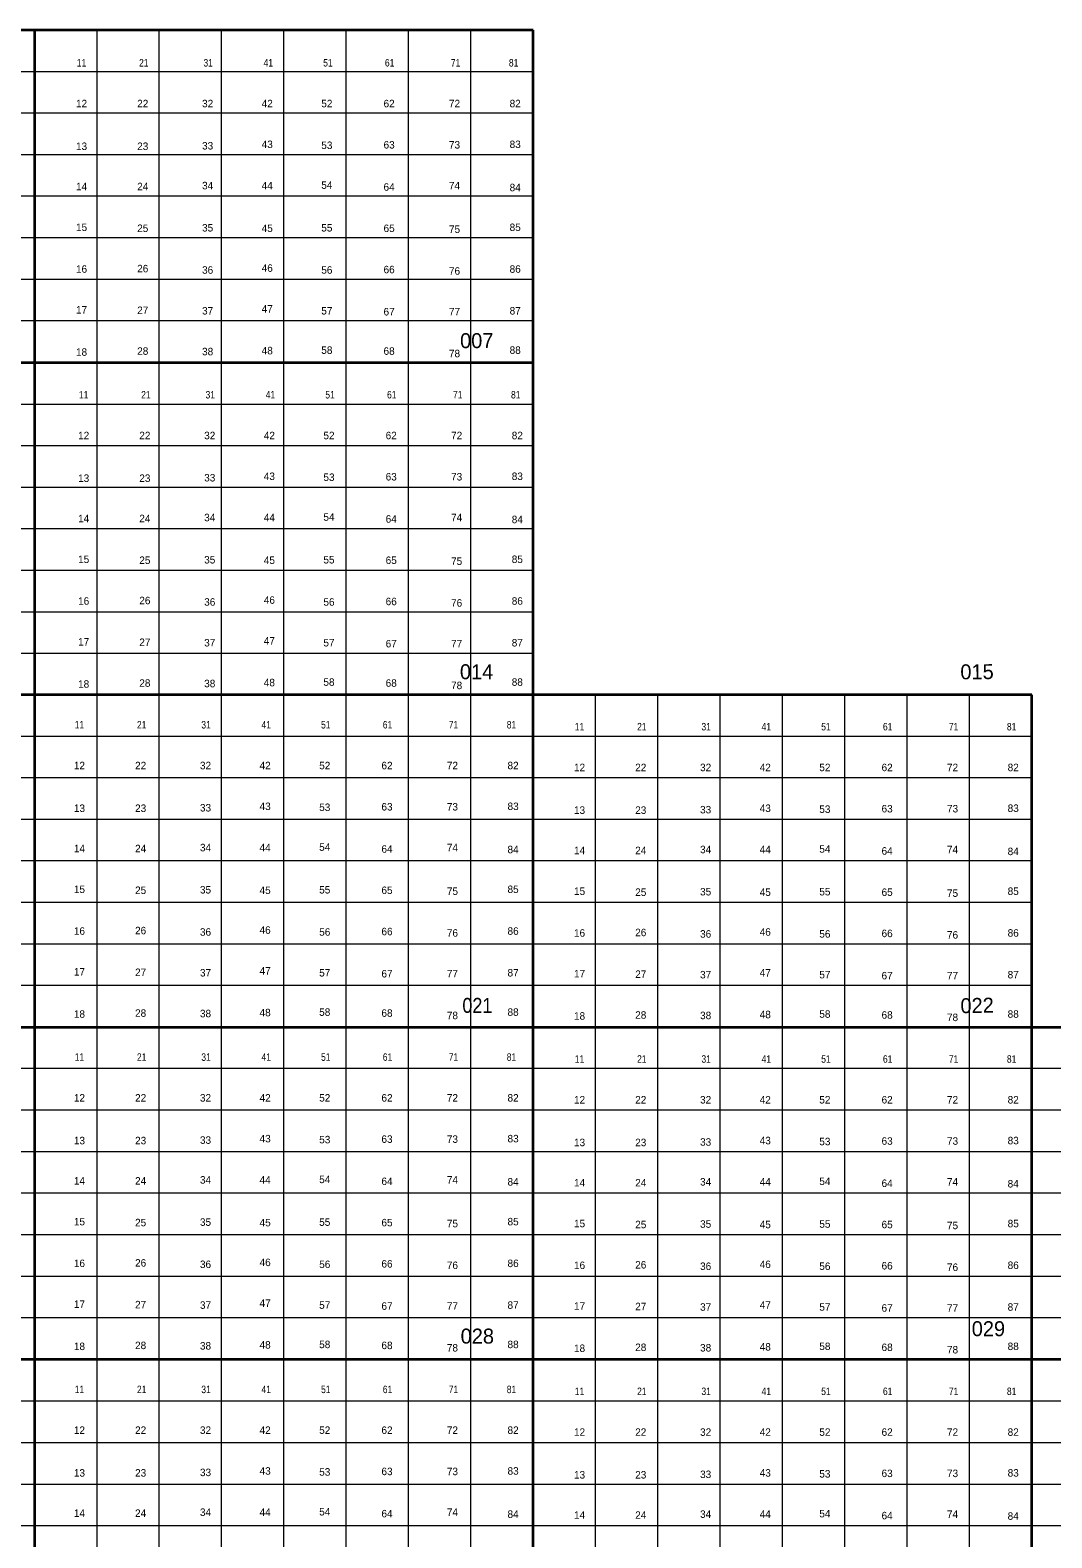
# Model space of a CAD drawing. Extents: x 639000 to 672000, y 222000 to 252000.
# Drawn here: x 653973 to 660121, y 242926 to 252000 of the extents above; entities that cross this region are included whole.
import ezdxf
from ezdxf.enums import TextEntityAlignment as Align

# ---------------------------------------------------------------- set-up
doc = ezdxf.new("R2010")
doc.units = 0
doc.header["$LTSCALE"] = 18
doc.layers.add('1', color=7, linetype='Continuous', lineweight=13)
doc.layers.add('2', color=7, linetype='Continuous')
doc.layers.add('29', color=7, linetype='Continuous')

msp = doc.modelspace()

# ---------------------------------------------------------------- linework, layer by layer
at = {"layer": '1', "lineweight": 35}
for p, q in [((657000, 252000), (648000, 252000)), ((654000, 222000), (654000, 252000)), ((657000, 222000), (657000, 252000)), ((645000, 250000), (657000, 250000)), ((660000, 248000), (639000, 248000)), ((660000, 222000), (660000, 248000)), ((639000, 246000), (663000, 246000)), ((666000, 244000), (639000, 244000))]:
    msp.add_line(p, q, dxfattribs=at)
at = {"layer": '1'}
for p, q in [((654375, 222000), (654375, 252000)), ((654750, 222000), (654750, 252000)), ((655125, 222000), (655125, 252000)), ((655500, 222000), (655500, 252000)), ((655875, 222000), (655875, 252000)), ((656250, 222000), (656250, 252000)), ((656625, 222000), (656625, 252000)), ((657000, 251750), (648000, 251750)), ((657000, 251500), (648000, 251500)), ((657000, 251250), (648000, 251250)), ((657000, 251000), (648000, 251000)), ((657000, 250750), (648000, 250750)), ((657000, 250500), (648000, 250500)), ((657000, 250250), (648000, 250250)), ((645000, 249750), (657000, 249750)), ((645000, 249500), (657000, 249500)), ((645000, 249250), (657000, 249250)), ((645000, 249000), (657000, 249000)), ((645000, 248750), (657000, 248750)), ((645000, 248500), (657000, 248500)), ((645000, 248250), (657000, 248250)), ((657375, 222000), (657375, 248000)), ((657750, 222000), (657750, 248000)), ((658125, 222000), (658125, 248000)), ((658500, 222000), (658500, 248000)), ((658875, 222000), (658875, 248000)), ((659250, 222000), (659250, 248000)), ((659625, 222000), (659625, 248000)), ((660000, 247750), (639000, 247750)), ((660000, 247500), (639000, 247500)), ((660000, 247250), (639000, 247250)), ((660000, 247000), (639000, 247000)), ((660000, 246750), (639000, 246750)), ((660000, 246500), (639000, 246500)), ((660000, 246250), (639000, 246250)), ((663000, 245750), (639000, 245750)), ((663000, 245500), (639000, 245500)), ((663000, 245250), (639000, 245250)), ((663000, 245000), (639000, 245000)), ((663000, 244750), (639000, 244750)), ((663000, 244500), (639000, 244500)), ((663000, 244250), (639000, 244250)), ((639000, 243750), (666000, 243750)), ((639000, 243500), (666000, 243500)), ((639000, 243250), (666000, 243250)), ((639000, 243000), (666000, 243000))]:
    msp.add_line(p, q, dxfattribs=at)

# ---------------------------------------------------------------- texts
at = {"layer": '2'}
for s, rotation, p in [('007', 0.15, (656660.31, 250086.42)), ('015', 0.43, (659670.93, 248093.82)), ('022', 1.29, (659672.21, 246085.5)), ('028', 359.94, (656663.46, 244095.54)), ('029', 359.94, (659739.05, 244140.04))]:
    msp.add_text(s, height=90, rotation=rotation, dxfattribs=at).set_placement(p, align=Align.CENTER)
msp.add_text('014', height=90, dxfattribs=at).set_placement((656659.17, 248093.9), align=Align.CENTER)
at = {"layer": '2', "width": 0.9}
msp.add_text('021', height=90, dxfattribs=at).set_placement((656663.84, 246085.74), align=Align.CENTER)
at = {"layer": '29', "width": 0.85}
for s, p in [('11', (654281.97, 251781.19)), ('21', (654656.57, 251781.19)), ('31', (655043.88, 251781.19)), ('41', (655405.78, 251781.19)), ('51', (655764.51, 251781.19)), ('61', (656135.94, 251781.19)), ('71', (656532.77, 251781.19)), ('81', (656881.97, 251781.19)), ('11', (654294.67, 249783.43)), ('21', (654669.27, 249783.43)), ('31', (655056.57, 249783.43)), ('41', (655418.48, 249783.43)), ('51', (655777.21, 249783.43)), ('61', (656148.64, 249783.43)), ('71', (656545.46, 249783.43)), ('81', (656894.67, 249783.43)), ('11', (654269.27, 247797.21)), ('21', (654643.88, 247797.21)), ('31', (655031.18, 247797.21)), ('41', (655393.08, 247797.21)), ('51', (655751.81, 247797.21)), ('61', (656123.24, 247797.21)), ('71', (656520.07, 247797.21)), ('81', (656869.28, 247797.21)), ('11', (657278.8, 247785.66)), ('21', (657653.4, 247785.66)), ('31', (658040.7, 247785.66)), ('41', (658402.61, 247785.66)), ('51', (658761.34, 247785.66)), ('61', (659132.77, 247785.66)), ('71', (659529.6, 247785.66)), ('81', (659878.8, 247785.66)), ('11', (654269.27, 245797.21)), ('21', (654643.88, 245797.21)), ('31', (655031.18, 245797.21)), ('41', (655393.08, 245797.21)), ('51', (655751.81, 245797.21)), ('61', (656123.24, 245797.21)), ('71', (656520.07, 245797.21)), ('81', (656869.28, 245797.21)), ('11', (657278.8, 245785.66)), ('21', (657653.4, 245785.66)), ('31', (658040.7, 245785.66)), ('41', (658402.61, 245785.66)), ('51', (658761.34, 245785.66)), ('61', (659132.77, 245785.66)), ('71', (659529.6, 245785.66)), ('81', (659878.8, 245785.66)), ('11', (654269.27, 243797.21)), ('21', (654643.88, 243797.21)), ('31', (655031.18, 243797.21)), ('41', (655393.08, 243797.21)), ('51', (655751.81, 243797.21)), ('61', (656123.24, 243797.21)), ('71', (656520.07, 243797.21)), ('81', (656869.28, 243797.21)), ('11', (657278.8, 243785.66)), ('21', (657653.4, 243785.66)), ('31', (658040.7, 243785.66)), ('41', (658402.61, 243785.66)), ('51', (658761.34, 243785.66)), ('61', (659132.77, 243785.66)), ('71', (659529.6, 243785.66)), ('81', (659878.8, 243785.66))]:
    msp.add_text(s, height=45, dxfattribs=at).set_placement(p, align=Align.CENTER)
at = {"layer": '29'}
for s, p in [('12', (654281.97, 251535.8)), ('22', (654650.22, 251535.8)), ('32', (655040.7, 251535.8)), ('42', (655399.43, 251535.8)), ('52', (655758.16, 251535.8)), ('62', (656132.76, 251535.8)), ('72', (656526.42, 251535.8)), ('82', (656891.5, 251535.8)), ('13', (654281.97, 251278.86)), ('23', (654650.22, 251278.86)), ('33', (655040.7, 251281.75)), ('43', (655399.43, 251290.41)), ('53', (655758.16, 251284.64)), ('63', (656132.77, 251287.53)), ('73', (656526.42, 251287.53)), ('83', (656891.5, 251290.41)), ('14', (654281.97, 251036.36)), ('24', (654650.22, 251036.36)), ('34', (655040.7, 251042.14)), ('44', (655399.43, 251042.14)), ('54', (655758.16, 251045.02)), ('64', (656132.77, 251033.48)), ('74', (656526.42, 251042.14)), ('84', (656891.5, 251030.59)), ('15', (654281.97, 250790.97)), ('25', (654650.22, 250785.2)), ('35', (655040.7, 250788.08)), ('45', (655399.43, 250785.2)), ('55', (655758.16, 250788.08)), ('65', (656132.77, 250785.2)), ('75', (656526.42, 250779.42)), ('85', (656891.5, 250790.97)), ('16', (654281.97, 250539.81)), ('26', (654650.22, 250542.69)), ('36', (655040.7, 250534.03)), ('46', (655399.43, 250545.58)), ('56', (655758.16, 250534.03)), ('66', (656132.77, 250536.92)), ('76', (656526.42, 250528.26)), ('86', (656891.5, 250539.81)), ('47', (655399.43, 250300.19)), ('17', (654281.97, 250294.42)), ('27', (654650.22, 250291.53)), ('37', (655040.7, 250288.64)), ('57', (655758.16, 250288.64)), ('67', (656132.77, 250282.87)), ('77', (656526.42, 250282.87)), ('87', (656891.5, 250288.64)), ('18', (654281.97, 250040.36)), ('28', (654650.22, 250046.14)), ('38', (655040.7, 250043.25)), ('48', (655399.43, 250049.03)), ('58', (655758.16, 250051.91)), ('68', (656132.76, 250046.14)), ('78', (656526.42, 250031.7)), ('88', (656891.5, 250051.91)), ('12', (654294.67, 249538.04)), ('22', (654662.92, 249538.04)), ('32', (655053.4, 249538.04)), ('42', (655412.13, 249538.04)), ('52', (655770.86, 249538.04)), ('62', (656145.46, 249538.04)), ('72', (656539.11, 249538.04)), ('82', (656904.19, 249538.04)), ('13', (654294.67, 249281.1)), ('23', (654662.92, 249281.1)), ('33', (655053.4, 249283.98)), ('43', (655412.13, 249292.65)), ('53', (655770.86, 249286.87)), ('63', (656145.46, 249289.76)), ('73', (656539.11, 249289.76)), ('83', (656904.19, 249292.65)), ('14', (654294.67, 249038.59)), ('24', (654662.92, 249038.59)), ('34', (655053.4, 249044.37)), ('44', (655412.13, 249044.37)), ('54', (655770.86, 249047.26)), ('64', (656145.46, 249035.71)), ('74', (656539.11, 249044.37)), ('84', (656904.19, 249032.82)), ('15', (654294.67, 248793.2)), ('25', (654662.92, 248787.43)), ('35', (655053.4, 248790.32)), ('45', (655412.13, 248787.43)), ('55', (655770.86, 248790.32)), ('65', (656145.46, 248787.43)), ('75', (656539.11, 248781.65)), ('85', (656904.19, 248793.2)), ('16', (654294.67, 248542.04)), ('26', (654662.92, 248544.93)), ('36', (655053.4, 248536.27)), ('46', (655412.13, 248547.81)), ('56', (655770.86, 248536.27)), ('66', (656145.46, 248539.15)), ('76', (656539.11, 248530.49)), ('86', (656904.19, 248542.04)), ('47', (655412.13, 248302.42)), ('17', (654294.67, 248296.65)), ('27', (654662.92, 248293.76)), ('37', (655053.4, 248290.88)), ('57', (655770.86, 248290.88)), ('67', (656145.46, 248285.1)), ('77', (656539.11, 248285.1)), ('87', (656904.19, 248290.88)), ('18', (654294.67, 248042.6)), ('28', (654662.92, 248048.37)), ('38', (655053.4, 248045.48)), ('48', (655412.13, 248051.26)), ('58', (655770.86, 248054.15)), ('68', (656145.46, 248048.37)), ('78', (656539.11, 248033.94)), ('88', (656904.19, 248054.15)), ('12', (654269.27, 247551.82)), ('22', (654637.53, 247551.82)), ('32', (655028, 247551.82)), ('42', (655386.73, 247551.82)), ('52', (655745.46, 247551.82)), ('62', (656120.07, 247551.82)), ('72', (656513.72, 247551.82)), ('82', (656878.8, 247551.82)), ('12', (657278.8, 247540.27)), ('22', (657647.05, 247540.27)), ('32', (658037.53, 247540.27)), ('42', (658396.26, 247540.27)), ('52', (658754.99, 247540.27)), ('62', (659129.59, 247540.27)), ('72', (659523.24, 247540.27)), ('82', (659888.32, 247540.27)), ('43', (655386.73, 247306.43)), ('63', (656120.07, 247303.54)), ('73', (656513.72, 247303.54)), ('83', (656878.8, 247306.43)), ('13', (654269.27, 247294.88)), ('23', (654637.53, 247294.88)), ('33', (655028, 247297.77)), ('53', (655745.46, 247300.65)), ('13', (657278.8, 247283.33)), ('23', (657647.05, 247283.33)), ('33', (658037.53, 247286.22)), ('43', (658396.26, 247294.88)), ('53', (658754.99, 247289.11)), ('63', (659129.59, 247291.99)), ('73', (659523.24, 247291.99)), ('83', (659888.33, 247294.88)), ('14', (654269.27, 247052.38)), ('24', (654637.53, 247052.38)), ('34', (655028, 247058.15)), ('44', (655386.73, 247058.15)), ('54', (655745.46, 247061.04)), ('64', (656120.07, 247049.49)), ('74', (656513.72, 247058.15)), ('84', (656878.8, 247046.6)), ('14', (657278.8, 247040.83)), ('24', (657647.05, 247040.83)), ('34', (658037.53, 247046.6)), ('44', (658396.26, 247046.6)), ('54', (658754.99, 247049.49)), ('64', (659129.59, 247037.94)), ('74', (659523.24, 247046.6)), ('84', (659888.33, 247035.05)), ('15', (654269.27, 246806.98)), ('25', (654637.53, 246801.21)), ('35', (655028, 246804.1)), ('45', (655386.73, 246801.21)), ('55', (655745.46, 246804.1)), ('65', (656120.07, 246801.21)), ('75', (656513.72, 246795.44)), ('85', (656878.8, 246806.99)), ('15', (657278.8, 246795.44)), ('25', (657647.05, 246789.66)), ('35', (658037.53, 246792.55)), ('45', (658396.26, 246789.66)), ('55', (658754.99, 246792.55)), ('65', (659129.59, 246789.66)), ('75', (659523.24, 246783.89)), ('85', (659888.33, 246795.44)), ('16', (654269.27, 246555.82)), ('26', (654637.53, 246558.71)), ('36', (655028, 246550.05)), ('46', (655386.73, 246561.59)), ('56', (655745.46, 246550.05)), ('66', (656120.07, 246552.93)), ('76', (656513.72, 246544.27)), ('86', (656878.8, 246555.82)), ('16', (657278.8, 246544.27)), ('26', (657647.05, 246547.16)), ('36', (658037.53, 246538.5)), ('46', (658396.26, 246550.05)), ('56', (658754.99, 246538.5)), ('66', (659129.59, 246541.39)), ('76', (659523.24, 246532.72)), ('86', (659888.33, 246544.27)), ('17', (654269.27, 246310.43)), ('27', (654637.53, 246307.54)), ('37', (655028, 246304.66)), ('47', (655386.73, 246316.2)), ('87', (656878.8, 246304.66)), ('57', (655745.46, 246304.66)), ('67', (656120.07, 246298.88)), ('77', (656513.72, 246298.88)), ('17', (657278.8, 246298.88)), ('27', (657647.05, 246295.99)), ('37', (658037.53, 246293.11)), ('47', (658396.26, 246304.65)), ('57', (658754.99, 246293.11)), ('67', (659129.59, 246287.33)), ('77', (659523.25, 246287.33)), ('87', (659888.33, 246293.11)), ('18', (654269.27, 246056.38)), ('28', (654637.53, 246062.15)), ('38', (655028, 246059.27)), ('48', (655386.73, 246065.04)), ('58', (655745.46, 246067.93)), ('68', (656120.07, 246062.15)), ('78', (656513.72, 246047.72)), ('88', (656878.8, 246067.93)), ('18', (657278.8, 246044.83)), ('28', (657647.05, 246050.6)), ('38', (658037.53, 246047.72)), ('48', (658396.26, 246053.49)), ('58', (658754.99, 246056.38)), ('68', (659129.59, 246050.6)), ('78', (659523.24, 246036.17)), ('88', (659888.32, 246056.38)), ('12', (654269.27, 245551.82)), ('22', (654637.53, 245551.82)), ('32', (655028, 245551.82)), ('42', (655386.73, 245551.82)), ('52', (655745.46, 245551.82)), ('62', (656120.07, 245551.82)), ('72', (656513.72, 245551.82)), ('82', (656878.8, 245551.82)), ('12', (657278.8, 245540.27)), ('22', (657647.05, 245540.27)), ('32', (658037.53, 245540.27)), ('42', (658396.26, 245540.27)), ('52', (658754.99, 245540.27)), ('62', (659129.59, 245540.27)), ('72', (659523.24, 245540.27)), ('82', (659888.32, 245540.27)), ('43', (655386.73, 245306.43)), ('83', (656878.8, 245306.43)), ('13', (654269.27, 245294.88)), ('23', (654637.53, 245294.88)), ('33', (655028, 245297.77)), ('53', (655745.46, 245300.65)), ('63', (656120.07, 245303.54)), ('73', (656513.72, 245303.54)), ('13', (657278.8, 245283.33)), ('23', (657647.05, 245283.33)), ('33', (658037.53, 245286.22)), ('43', (658396.26, 245294.88)), ('53', (658754.99, 245289.11)), ('63', (659129.59, 245291.99)), ('73', (659523.24, 245291.99)), ('83', (659888.33, 245294.88)), ('14', (654269.27, 245052.38)), ('24', (654637.53, 245052.38)), ('34', (655028, 245058.15)), ('44', (655386.73, 245058.15)), ('54', (655745.46, 245061.04)), ('64', (656120.07, 245049.49)), ('74', (656513.72, 245058.15)), ('84', (656878.8, 245046.6)), ('14', (657278.8, 245040.83)), ('24', (657647.05, 245040.83)), ('34', (658037.53, 245046.6)), ('44', (658396.26, 245046.6)), ('54', (658754.99, 245049.49)), ('64', (659129.59, 245037.94)), ('74', (659523.24, 245046.6)), ('84', (659888.33, 245035.05)), ('15', (654269.27, 244806.98)), ('25', (654637.53, 244801.21)), ('35', (655028, 244804.1)), ('45', (655386.73, 244801.21)), ('55', (655745.46, 244804.1)), ('65', (656120.07, 244801.21)), ('75', (656513.72, 244795.44)), ('85', (656878.8, 244806.99)), ('15', (657278.8, 244795.44)), ('25', (657647.05, 244789.66)), ('35', (658037.53, 244792.55)), ('45', (658396.26, 244789.66)), ('55', (658754.99, 244792.55)), ('65', (659129.59, 244789.66)), ('75', (659523.24, 244783.89)), ('85', (659888.33, 244795.44)), ('16', (654269.27, 244555.82)), ('26', (654637.53, 244558.71)), ('36', (655028, 244550.05)), ('46', (655386.73, 244561.59)), ('56', (655745.46, 244550.05)), ('66', (656120.07, 244552.93)), ('76', (656513.72, 244544.27)), ('86', (656878.8, 244555.82)), ('16', (657278.8, 244544.27)), ('26', (657647.05, 244547.16)), ('36', (658037.53, 244538.5)), ('46', (658396.26, 244550.05)), ('56', (658754.99, 244538.5)), ('66', (659129.59, 244541.39)), ('76', (659523.24, 244532.72)), ('86', (659888.33, 244544.27)), ('17', (654269.27, 244310.43)), ('47', (655386.73, 244316.2)), ('27', (654637.53, 244307.54)), ('37', (655028, 244304.66)), ('57', (655745.46, 244304.66)), ('67', (656120.07, 244298.88)), ('77', (656513.72, 244298.88)), ('87', (656878.8, 244304.66)), ('17', (657278.8, 244298.88)), ('27', (657647.05, 244295.99)), ('37', (658037.53, 244293.11)), ('47', (658396.26, 244304.65)), ('57', (658754.99, 244293.11)), ('67', (659129.59, 244287.33)), ('77', (659523.25, 244287.33)), ('87', (659888.33, 244293.11)), ('18', (654269.27, 244056.38)), ('28', (654637.53, 244062.15)), ('38', (655028, 244059.27)), ('48', (655386.73, 244065.04)), ('58', (655745.46, 244067.93)), ('68', (656120.07, 244062.15)), ('78', (656513.72, 244047.72)), ('88', (656878.8, 244067.93)), ('18', (657278.8, 244044.83)), ('28', (657647.05, 244050.6)), ('38', (658037.53, 244047.72)), ('48', (658396.26, 244053.49)), ('58', (658754.99, 244056.38)), ('68', (659129.59, 244050.6)), ('78', (659523.24, 244036.17)), ('88', (659888.32, 244056.38)), ('12', (654269.27, 243551.82)), ('22', (654637.53, 243551.82)), ('32', (655028, 243551.82)), ('42', (655386.73, 243551.82)), ('52', (655745.46, 243551.82)), ('62', (656120.07, 243551.82)), ('72', (656513.72, 243551.82)), ('82', (656878.8, 243551.82)), ('12', (657278.8, 243540.27)), ('22', (657647.05, 243540.27)), ('32', (658037.53, 243540.27)), ('42', (658396.26, 243540.27)), ('52', (658754.99, 243540.27)), ('62', (659129.59, 243540.27)), ('72', (659523.24, 243540.27)), ('82', (659888.32, 243540.27)), ('13', (654269.27, 243294.88)), ('23', (654637.53, 243294.88)), ('33', (655028, 243297.77)), ('43', (655386.73, 243306.43)), ('53', (655745.46, 243300.65)), ('63', (656120.07, 243303.54)), ('73', (656513.72, 243303.54)), ('83', (656878.8, 243306.43)), ('13', (657278.8, 243283.33)), ('23', (657647.05, 243283.33)), ('33', (658037.53, 243286.22)), ('43', (658396.26, 243294.88)), ('53', (658754.99, 243289.11)), ('63', (659129.59, 243291.99)), ('73', (659523.24, 243291.99)), ('83', (659888.33, 243294.88)), ('14', (654269.27, 243052.38)), ('24', (654637.53, 243052.38)), ('34', (655028, 243058.15)), ('44', (655386.73, 243058.15)), ('54', (655745.46, 243061.04)), ('64', (656120.07, 243049.49)), ('74', (656513.72, 243058.15)), ('84', (656878.8, 243046.6)), ('14', (657278.8, 243040.83)), ('24', (657647.05, 243040.83)), ('34', (658037.53, 243046.6)), ('44', (658396.26, 243046.6)), ('54', (658754.99, 243049.49)), ('64', (659129.59, 243037.94)), ('74', (659523.24, 243046.6)), ('84', (659888.33, 243035.05))]:
    msp.add_text(s, height=45, dxfattribs=at).set_placement(p, align=Align.CENTER)

doc.saveas('drawing.dxf')
